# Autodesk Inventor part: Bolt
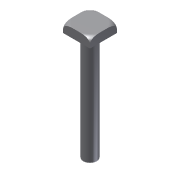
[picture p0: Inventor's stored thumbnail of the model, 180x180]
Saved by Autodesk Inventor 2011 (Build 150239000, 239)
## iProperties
Created: 2009-04
Part Number: Bolt
Document SubType Name: Modeling
Designer: Sham
Density: 1 g/cm^3
Mass: 15.4148 g
Surface Area: 54.8703 cm^2
Volume: 15.4148 cm^3
Author: Sham
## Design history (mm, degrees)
sketch "Sketch1"
  geometry: L1 (-12, 12)-(12, 12); L2 (12, 12)-(12, -12); L3 (12, -12)-(-12, -12); L4 (-12, -12)-(-12, 12); 1 further point
  constraints: 8 end point, 2 parallel, 2 perpendicular, 1 horizontal, 1 other
  dimensions: "d0" = 24 distance of L1.start L1.end; "d1" = 12 distance from line of L2 point (0, 0); "d2" = 12 distance from line of L1 point (0, 0)
extrude "Extrusion1" new body sketch "Sketch1" distance "d3" = 8; taper "d4" = 0 deg
sketch "Sketch2"
  geometry: C1 r 6 at (0, 0)
  constraints: 1 centre point
  dimensions: "d5" = 12 diameter of C1
extrude "Extrusion2" join sketch "Sketch2" distance "d6" = 96; taper "d7" = 0 deg
workpoint "Work Point1"
workplane "Work Plane1"
sketch "Sketch3"
  geometry: L1 (33.941, 5)-(33.941, 6); L2 (28.941, 0)-(28.405, 0); L3 (16.971, 125.007)-(16.971, -22.043) reference; A1 r 5 centre (28.941, 5) between (28.941, 0) and (33.941, 5); 1 further point
  constraints: 4 end point, 2 point on circle, 2 point on line, 2 tangent, 1 centre point, 1 perpendicular
  dimensions: "d10" = 5 radius of A1
revolve "Revolution1" sketch "Sketch3" stored, may be unused: angle "d12" = 90 deg
body "Solid1"
other parameters: "d11" = 90 deg
